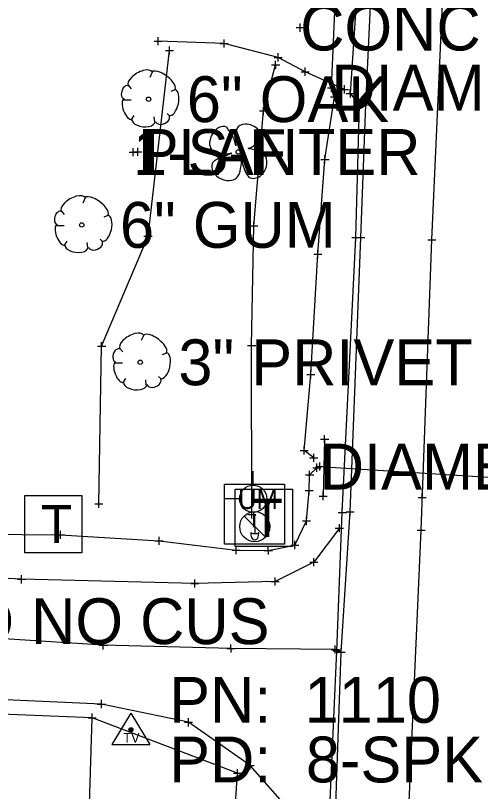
# Model space of a CAD drawing. Extents: x -1 to 1157254, y -1 to 2021979.
# Drawn here: x 1150326.7 to 1150399.8, y 2020191.5 to 2020313.4 of the extents above; entities that cross this region are included whole.
import ezdxf

# ---------------------------------------------------------------- set-up
doc = ezdxf.new("R2010")
doc.units = 0
for name, color, linetype in [('S_BREAKLINE', 7, 'Continuous'), ('S_BUILDING_ANNOT', 7, 'Continuous'), ('S_CAL_CORNER', 7, 'Continuous'), ('S_CATCH_BASIN', 7, 'Continuous'), ('S_CATCH_BASIN_ANNOT', 7, 'Continuous'), ('S_CTL_TABLE', 7, 'Continuous'), ('S_CURB', 7, 'Continuous'), ('S_DRIVEWAY_ANNOT', 7, 'Continuous'), ('S_DROP_INLET_ANNOT', 7, 'Continuous'), ('S_EDGE_BITUMINOUS_ANNOT', 7, 'Continuous'), ('S_EDGE_CONCRETE', 7, 'Continuous'), ('S_EDGE_CONCRETE_ANNOT', 7, 'Continuous'), ('S_ELECTRIC_UTILITIES_ANNOT', 7, 'Continuous'), ('S_ENV_CONSTRAINT', 7, 'Continuous'), ('S_EXIST_ROW', 7, 'Continuous'), ('S_FLAG_POLE', 7, 'Continuous'), ('S_GAS_UTILITIES_ANNOT', 7, 'Continuous'), ('S_GATE', 7, 'Continuous'), ('S_GATE_ANNOT', 7, 'Continuous')]:
    doc.layers.add(name, color=color, linetype=linetype)

msp = doc.modelspace()

# ---------------------------------------------------------------- linework, layer by layer
at = {"layer": 'S_BREAKLINE'}
for p, q in [((1150344.87, 2020203.83), (1150341.86, 2020198.88)), ((1150344.87, 2020203.83), (1150347.82, 2020198.88)), ((1150341.86, 2020198.88), (1150347.82, 2020198.88))]:
    msp.add_line(p, q, dxfattribs=at)
for radius in [0.311, 0.183, 0.103]:
    msp.add_circle((1150344.87, 2020201.23), radius, dxfattribs=at)
at = {"layer": 'S_BUILDING_ANNOT'}
for p, q in [((1150370.81, 2020311.48), (1150372.09, 2020311.48)), ((1150371.45, 2020310.84), (1150371.45, 2020312.11)), ((1150371.45, 2020311.48), (1150371.45, 2020311.48)), ((1150348.5, 2020309.34), (1150349.78, 2020309.34)), ((1150349.14, 2020308.7), (1150349.14, 2020309.97)), ((1150349.14, 2020309.34), (1150349.14, 2020309.34)), ((1150358.85, 2020308.97), (1150360.12, 2020308.97)), ((1150359.49, 2020308.34), (1150359.49, 2020309.61)), ((1150359.49, 2020308.97), (1150359.49, 2020308.97)), ((1150367.35, 2020306.8), (1150368.62, 2020306.8)), ((1150367.99, 2020306.17), (1150367.99, 2020307.44)), ((1150367.99, 2020306.8), (1150367.99, 2020306.8)), ((1150371.58, 2020304.55), (1150372.85, 2020304.55)), ((1150372.22, 2020303.92), (1150372.21, 2020305.19)), ((1150372.21, 2020304.55), (1150372.21, 2020304.55)), ((1150375.72, 2020302.04), (1150377, 2020302.04)), ((1150376.36, 2020301.41), (1150376.36, 2020302.68)), ((1150376.36, 2020302.04), (1150376.36, 2020302.04)), ((1150377.76, 2020301.78), (1150379.04, 2020301.78)), ((1150378.4, 2020301.15), (1150378.4, 2020302.42)), ((1150378.4, 2020301.78), (1150378.4, 2020301.78)), ((1150379.33, 2020300.52), (1150379.32, 2020301.79)), ((1150376.19, 2020300.62), (1150377.46, 2020300.62)), ((1150376.83, 2020299.98), (1150376.82, 2020301.25)), ((1150376.83, 2020300.62), (1150376.83, 2020300.62)), ((1150378.69, 2020301.15), (1150379.96, 2020301.15)), ((1150379.33, 2020301.15), (1150379.33, 2020301.15)), ((1150380.15, 2020299.35), (1150381.43, 2020299.35)), ((1150380.79, 2020298.72), (1150380.79, 2020299.99)), ((1150380.79, 2020299.35), (1150380.79, 2020299.35)), ((1150381.14, 2020299.32), (1150382.42, 2020299.33)), ((1150381.78, 2020298.69), (1150381.78, 2020299.96)), ((1150381.78, 2020299.33), (1150381.78, 2020299.33)), ((1150344.57, 2020291.92), (1150345.84, 2020291.92)), ((1150345.21, 2020291.29), (1150345.2, 2020292.56)), ((1150345.2, 2020291.92), (1150345.2, 2020291.92)), ((1150345.31, 2020291.95), (1150346.58, 2020291.95)), ((1150345.95, 2020291.32), (1150345.95, 2020292.59)), ((1150345.95, 2020291.95), (1150345.95, 2020291.95)), ((1150374.7, 2020290.75), (1150375.98, 2020290.76)), ((1150375.34, 2020290.12), (1150375.34, 2020291.39)), ((1150375.34, 2020290.75), (1150375.34, 2020290.75)), ((1150379.57, 2020278.54), (1150380.84, 2020278.54)), ((1150380.21, 2020277.9), (1150380.2, 2020279.18)), ((1150380.21, 2020278.54), (1150380.21, 2020278.54)), ((1150380.35, 2020278.5), (1150381.63, 2020278.5)), ((1150380.99, 2020277.86), (1150380.99, 2020279.13)), ((1150380.99, 2020278.5), (1150380.99, 2020278.5)), ((1150392.14, 2020277.51), (1150392.13, 2020278.78)), ((1150391.5, 2020278.14), (1150392.77, 2020278.15)), ((1150392.14, 2020278.15), (1150392.14, 2020278.15)), ((1150374.23, 2020275.25), (1150374.22, 2020276.52)), ((1150373.59, 2020275.88), (1150374.86, 2020275.88)), ((1150374.22, 2020275.88), (1150374.22, 2020275.88)), ((1150372.49, 2020257.02), (1150373.76, 2020257.02)), ((1150373.13, 2020256.38), (1150373.13, 2020257.65)), ((1150373.13, 2020257.02), (1150373.13, 2020257.02)), ((1150374.66, 2020246.84), (1150375.93, 2020246.85)), ((1150375.29, 2020246.21), (1150375.29, 2020247.48)), ((1150375.29, 2020246.84), (1150375.29, 2020246.84)), ((1150372.08, 2020244.42), (1150372.08, 2020245.69)), ((1150371.45, 2020245.06), (1150372.72, 2020245.06)), ((1150372.08, 2020245.06), (1150372.08, 2020245.06)), ((1150373.58, 2020243.28), (1150373.58, 2020244.55)), ((1150372.94, 2020243.91), (1150374.21, 2020243.91)), ((1150373.58, 2020243.91), (1150373.58, 2020243.91)), ((1150374.53, 2020241.91), (1150374.53, 2020243.18)), ((1150372.93, 2020240.62), (1150372.93, 2020241.9)), ((1150373.45, 2020242.37), (1150374.72, 2020242.37)), ((1150373.89, 2020242.54), (1150375.16, 2020242.55)), ((1150374.09, 2020241.74), (1150374.09, 2020243.01)), ((1150374.09, 2020242.37), (1150374.09, 2020242.37)), ((1150374.53, 2020242.54), (1150374.53, 2020242.54)), ((1150372.29, 2020241.26), (1150373.57, 2020241.26)), ((1150372.93, 2020241.26), (1150372.93, 2020241.26)), ((1150372.23, 2020238.77), (1150373.5, 2020238.78)), ((1150372.87, 2020238.14), (1150372.86, 2020239.41)), ((1150372.87, 2020238.78), (1150372.87, 2020238.78)), ((1150375.05, 2020237.29), (1150375.05, 2020238.56)), ((1150390.63, 2020237.05), (1150390.62, 2020238.32)), ((1150390.63, 2020237.05), (1150390.62, 2020238.32)), ((1150374.41, 2020237.92), (1150375.68, 2020237.92)), ((1150375.05, 2020237.92), (1150375.05, 2020237.92)), ((1150389.99, 2020237.68), (1150391.26, 2020237.69)), ((1150389.99, 2020237.68), (1150391.26, 2020237.69)), ((1150390.63, 2020237.69), (1150390.63, 2020237.69)), ((1150390.63, 2020237.69), (1150390.63, 2020237.69)), ((1150378.07, 2020234.7), (1150378.07, 2020235.98)), ((1150379.28, 2020234.81), (1150379.28, 2020236.08)), ((1150372.43, 2020233.37), (1150372.42, 2020234.65)), ((1150377.43, 2020235.34), (1150378.7, 2020235.34)), ((1150378.07, 2020235.34), (1150378.07, 2020235.34)), ((1150378.65, 2020235.44), (1150379.92, 2020235.45)), ((1150379.28, 2020235.44), (1150379.28, 2020235.44)), ((1150371.79, 2020234.01), (1150373.06, 2020234.01)), ((1150372.42, 2020234.01), (1150372.42, 2020234.01)), ((1150377.6, 2020232.25), (1150377.6, 2020233.52)), ((1150333.8, 2020231.18), (1150333.79, 2020232.45)), ((1150376.96, 2020232.89), (1150378.24, 2020232.89)), ((1150377.6, 2020232.89), (1150377.6, 2020232.89)), ((1150389.82, 2020232.55), (1150391.09, 2020232.55)), ((1150390.45, 2020231.91), (1150390.45, 2020233.19)), ((1150390.45, 2020232.55), (1150390.45, 2020232.55)), ((1150333.16, 2020231.81), (1150334.43, 2020231.81)), ((1150333.79, 2020231.81), (1150333.79, 2020231.81)), ((1150349.29, 2020230.23), (1150349.29, 2020231.5)), ((1150348.65, 2020230.87), (1150349.93, 2020230.87)), ((1150349.29, 2020230.87), (1150349.29, 2020230.87)), ((1150361.39, 2020228.79), (1150361.39, 2020230.06)), ((1150366.45, 2020228.75), (1150366.44, 2020230.02)), ((1150369.97, 2020230.22), (1150371.24, 2020230.22)), ((1150370.61, 2020229.58), (1150370.6, 2020230.86)), ((1150370.6, 2020230.22), (1150370.6, 2020230.22)), ((1150360.76, 2020229.43), (1150362.03, 2020229.43)), ((1150361.39, 2020229.43), (1150361.39, 2020229.43)), ((1150365.81, 2020229.38), (1150367.08, 2020229.39)), ((1150366.44, 2020229.39), (1150366.44, 2020229.39)), ((1150372.96, 2020227.52), (1150374.23, 2020227.53)), ((1150373.6, 2020226.89), (1150373.6, 2020228.16)), ((1150373.6, 2020227.53), (1150373.6, 2020227.53)), ((1150327.06, 2020224.84), (1150328.33, 2020224.84)), ((1150327.69, 2020224.2), (1150327.69, 2020225.47)), ((1150327.69, 2020224.84), (1150327.69, 2020224.84)), ((1150367.53, 2020223.85), (1150367.53, 2020225.12)), ((1150354.25, 2020224.17), (1150355.52, 2020224.17)), ((1150354.89, 2020223.53), (1150354.88, 2020224.81)), ((1150354.89, 2020224.17), (1150354.89, 2020224.17)), ((1150366.9, 2020224.48), (1150368.17, 2020224.48)), ((1150367.53, 2020224.48), (1150367.53, 2020224.48)), ((1150340.53, 2020213.84), (1150340.53, 2020215.12)), ((1150339.89, 2020214.48), (1150341.17, 2020214.48)), ((1150340.53, 2020214.48), (1150340.53, 2020214.48)), ((1150359.95, 2020213.97), (1150361.22, 2020213.97)), ((1150360.59, 2020213.33), (1150360.58, 2020214.6)), ((1150360.59, 2020213.97), (1150360.59, 2020213.97)), ((1150376.96, 2020213.19), (1150376.96, 2020214.46)), ((1150377.22, 2020212.96), (1150377.21, 2020214.23)), ((1150377.87, 2020212.76), (1150377.87, 2020214.03)), ((1150376.33, 2020213.82), (1150377.6, 2020213.83)), ((1150376.58, 2020213.59), (1150377.85, 2020213.6)), ((1150376.96, 2020213.82), (1150376.96, 2020213.82)), ((1150377.22, 2020213.59), (1150377.22, 2020213.59)), ((1150377.23, 2020213.39), (1150378.51, 2020213.39)), ((1150377.87, 2020213.39), (1150377.87, 2020213.39)), ((1150340.22, 2020204.62), (1150340.22, 2020205.9)), ((1150339.59, 2020205.26), (1150340.86, 2020205.26)), ((1150340.22, 2020205.26), (1150340.22, 2020205.26)), ((1150353.92, 2020201.75), (1150353.92, 2020203.02)), ((1150353.28, 2020202.39), (1150354.55, 2020202.39)), ((1150353.92, 2020202.39), (1150353.92, 2020202.39)), ((1150362.97, 2020195.61), (1150364.24, 2020195.61)), ((1150363.61, 2020194.97), (1150363.61, 2020196.25)), ((1150363.61, 2020195.61), (1150363.61, 2020195.61))]:
    msp.add_line(p, q, dxfattribs=at)
at = {"layer": 'S_CAL_CORNER'}
for p, q in [((1150362.65, 2020234.78), (1150365.99, 2020231.44)), ((1150364.17, 2020235), (1150364.48, 2020235)), ((1150364.32, 2020233.11), (1150364.32, 2020234.84)), ((1150363.72, 2020232.21), (1150363.72, 2020232.02)), ((1150364.32, 2020233.11), (1150364.32, 2020232.05)), ((1150364.92, 2020232.21), (1150364.93, 2020231.98))]:
    msp.add_line(p, q, dxfattribs=at)
msp.add_lwpolyline([(1150359.56, 2020239.77), (1150368.97, 2020239.77), (1150368.97, 2020230.36), (1150359.56, 2020230.36)], close=True, dxfattribs=at)
msp.add_circle((1150364.32, 2020233.11), 2.36, dxfattribs=at)
for centre, radius, start, end in [((1150364.32, 2020235), 0.156, 180, 0), ((1150364.15, 2020232.6), 0.58, 223.1344, 287.472), ((1150364.5, 2020232.61), 0.58, 252.528, 316.8656)]:
    msp.add_arc(centre, radius, start, end, dxfattribs=at)
msp.add_ellipse((1150364.32, 2020231.86), major_axis=(0, -0.82), ratio=0.744362, start_param=4.519801, end_param=8.000179, dxfattribs=at)
at = {"layer": 'S_CATCH_BASIN'}
for p, q in [((1150364.07, 2020239.6), (1150364.07, 2020241.84)), ((1150361.98, 2020237.47), (1150359.65, 2020237.47)), ((1150364.15, 2020233.05), (1150364.15, 2020235.37))]:
    msp.add_line(p, q, dxfattribs=at)
msp.add_circle((1150364.07, 2020237.49), 2.13, dxfattribs=at)
at = {"layer": 'S_CATCH_BASIN_ANNOT'}
for points in [[(1150361.24, 2020230), (1150361.24, 2020239), (1150370.23, 2020239), (1150370.23, 2020230)], [(1150328.18, 2020229.02), (1150328.18, 2020238.02), (1150337.18, 2020238.02), (1150337.18, 2020229.02)]]:
    msp.add_lwpolyline(points, close=True, dxfattribs=at)
at = {"layer": 'S_CTL_TABLE'}
for p, q in [((1150350.28, 2020307.86), (1150351.55, 2020307.86)), ((1150350.92, 2020307.23), (1150350.91, 2020308.5)), ((1150350.91, 2020307.86), (1150350.91, 2020307.86)), ((1150366.97, 2020305.62), (1150368.24, 2020305.62)), ((1150367.61, 2020304.98), (1150367.6, 2020306.25)), ((1150367.6, 2020305.62), (1150367.6, 2020305.62)), ((1150365.05, 2020298.4), (1150366.32, 2020298.41)), ((1150365.69, 2020297.77), (1150365.68, 2020299.04)), ((1150365.69, 2020298.4), (1150365.69, 2020298.4)), ((1150364.16, 2020279.72), (1150364.16, 2020280.99)), ((1150363.52, 2020280.36), (1150364.79, 2020280.36)), ((1150364.16, 2020280.36), (1150364.16, 2020280.36)), ((1150346.91, 2020278.72), (1150348.18, 2020278.73)), ((1150347.55, 2020278.09), (1150347.54, 2020279.36)), ((1150347.55, 2020278.73), (1150347.55, 2020278.73)), ((1150339.63, 2020261.47), (1150340.9, 2020261.47)), ((1150340.27, 2020260.83), (1150340.27, 2020262.1)), ((1150340.27, 2020261.47), (1150340.27, 2020261.47)), ((1150363.18, 2020261.54), (1150364.46, 2020261.54)), ((1150363.82, 2020260.9), (1150363.82, 2020262.18)), ((1150363.82, 2020261.54), (1150363.82, 2020261.54)), ((1150339.84, 2020236.07), (1150339.84, 2020237.34)), ((1150339.21, 2020236.71), (1150340.48, 2020236.71)), ((1150339.84, 2020236.71), (1150339.84, 2020236.71)), ((1150363.21, 2020235.02), (1150364.49, 2020235.02)), ((1150363.85, 2020234.39), (1150363.85, 2020235.66)), ((1150363.85, 2020235.02), (1150363.85, 2020235.02)), ((1150338.14, 2020203.11), (1150339.41, 2020203.11)), ((1150338.15, 2020203.11), (1150339.42, 2020203.11)), ((1150338.78, 2020202.48), (1150338.78, 2020203.75)), ((1150338.78, 2020203.11), (1150338.78, 2020203.11)), ((1150338.79, 2020202.47), (1150338.79, 2020203.75)), ((1150338.79, 2020203.11), (1150338.79, 2020203.11)), ((1150360.99, 2020194.38), (1150362.27, 2020194.39)), ((1150361.63, 2020193.75), (1150361.63, 2020195.02)), ((1150361.63, 2020194.38), (1150361.63, 2020194.38))]:
    msp.add_line(p, q, dxfattribs=at)
at = {"layer": 'S_CURB'}
for p, q in [((1150348.21, 2020304.48), (1150347.83, 2020303.63)), ((1150344.42, 2020302.46), (1150344.92, 2020301.88)), ((1150351.78, 2020301.69), (1150351.12, 2020301.42)), ((1150343.76, 2020300.14), (1150344.88, 2020300.14)), ((1150351, 2020297.58), (1150350.54, 2020298.01)), ((1150344.92, 2020296.96), (1150345.39, 2020297.66)), ((1150348.6, 2020296.69), (1150348.52, 2020297.47)), ((1150361.35, 2020292.93), (1150361.11, 2020293.82)), ((1150363.3, 2020292.47), (1150363.68, 2020292.63)), ((1150360.7, 2020291.77), (1150359.73, 2020291.55)), ((1150362.24, 2020290.84), (1150362.32, 2020290.4)), ((1150337.69, 2020284.75), (1150337.31, 2020283.9)), ((1150333.9, 2020282.73), (1150334.4, 2020282.15)), ((1150341.26, 2020281.96), (1150340.6, 2020281.69)), ((1150333.24, 2020280.41), (1150334.36, 2020280.41)), ((1150334.4, 2020277.23), (1150334.87, 2020277.93)), ((1150338.08, 2020276.96), (1150338, 2020277.74)), ((1150340.48, 2020277.85), (1150340.02, 2020278.28)), ((1150346.88, 2020263.17), (1150346.49, 2020262.32)), ((1150343.08, 2020261.15), (1150343.59, 2020260.57)), ((1150350.44, 2020260.38), (1150349.78, 2020260.11)), ((1150342.42, 2020258.83), (1150343.55, 2020258.83)), ((1150349.67, 2020256.27), (1150349.2, 2020256.7)), ((1150343.59, 2020255.65), (1150344.05, 2020256.35)), ((1150347.27, 2020255.38), (1150347.19, 2020256.16))]:
    msp.add_line(p, q, dxfattribs=at)
for centre in [(1150347.65, 2020300.24), (1150361.72, 2020291.95), (1150337.14, 2020280.5), (1150346.32, 2020258.92)]:
    msp.add_circle(centre, 0.34, dxfattribs=at)
for centre, major_axis, ratio, start_param, end_param in [((1150346.32, 2020303.44), (1.86, 1.08), 0.471018, 0, 3.141593), ((1150349.97, 2020303.11), (-1.81, 1.36), 0.405113, 3.141593, 6.283186), ((1150344.09, 2020301.32), (0.31, 1.03), 0.646762, 0, 3.141593), ((1150351.33, 2020299.71), (0.46, 2.04), 0.482994, 3.141593, 6.283185), ((1150344.39, 2020298.67), (-0.61, 1.6), 0.420543, 6.283185, 9.424777), ((1150346.85, 2020296.89), (-1.83, 0.19), 0.529943, 0, 3.141593), ((1150349.81, 2020297.19), (1.09, 0.46), 0.711534, 3.141592, 6.283185), ((1150358.84, 2020293.97), (-1.03, -1.88), 0.662338, 3.141593, 6.283185), ((1150360.49, 2020294.84), (0.62, -1.01), 0.083512, 0, 3.141593), ((1150361.42, 2020294.26), (-0.07, -1.33), 0.068203, 3.141593, 6.283185), ((1150363.38, 2020294.84), (1.89, -0.74), 0.673998, 0, 3.141593), ((1150364.48, 2020293.36), (-0.798, -0.73), 0.092159, 0, 3.141593), ((1150358.77, 2020291.82), (0.963, -0.267), 0.113563, 3.141593, 6.283185), ((1150364.26, 2020292.24), (0.96, -0.23), 0.056001, 0, 3.141593), ((1150364.34, 2020289.97), (0.88, 2.05), 0.81717, 3.141593, 6.283185), ((1150358.15, 2020290.56), (0.477, 0.328), 0.136309, 0, 3.141593), ((1150359.67, 2020291.33), (1.04, 0.44), 0.002756, 3.141593, 6.283185), ((1150362, 2020289.67), (0.19, 1.31), 0.114148, 3.141593, 5.822668), ((1150359.74, 2020289.29), (2.07, -0.93), 0.760068, 3.141593, 6.283185), ((1150362.57, 2020289.63), (0.254, -0.771), 0.051603, 3.141593, 6.283185), ((1150363.15, 2020288.39), (-0.321, 0.467), 0.094289, 0, 3.141593), ((1150335.8, 2020283.7), (1.86, 1.08), 0.471018, 0, 3.141593), ((1150339.45, 2020283.38), (-1.81, 1.36), 0.405113, 3.141593, 6.283186), ((1150333.57, 2020281.59), (0.31, 1.03), 0.646762, 0, 3.141593), ((1150340.81, 2020279.97), (0.46, 2.04), 0.482994, 3.141593, 6.283185), ((1150333.87, 2020278.94), (-0.61, 1.6), 0.420543, 6.283185, 9.424777), ((1150336.33, 2020277.16), (-1.83, 0.19), 0.529943, 0, 3.141593), ((1150339.29, 2020277.45), (1.09, 0.46), 0.711534, 3.141592, 6.283185), ((1150344.98, 2020262.12), (1.86, 1.08), 0.471018, 0, 3.141593), ((1150348.64, 2020261.8), (-1.81, 1.36), 0.405113, 3.141593, 6.283186), ((1150342.75, 2020260.01), (0.31, 1.03), 0.646762, 0, 3.141593), ((1150349.99, 2020258.39), (0.46, 2.04), 0.482994, 3.141593, 6.283185), ((1150343.06, 2020257.36), (-0.61, 1.6), 0.420543, 6.283185, 9.424777), ((1150345.52, 2020255.58), (-1.83, 0.19), 0.529943, 0, 3.141593), ((1150348.47, 2020255.87), (1.09, 0.46), 0.711534, 3.141592, 6.283185)]:
    msp.add_ellipse(centre, major_axis=major_axis, ratio=ratio, start_param=start_param, end_param=end_param, dxfattribs=at)
at = {"layer": 'S_DRIVEWAY_ANNOT'}
for points in [[(1150373.58, 2020243.91), (1150372.08, 2020245.06), (1150373.13, 2020257.02), (1150374.22, 2020275.88), (1150375.34, 2020290.75), (1150376.83, 2020300.62)], [(1150309.59, 2020232.06), (1150333.79, 2020231.81), (1150349.29, 2020230.87), (1150361.39, 2020229.43), (1150366.44, 2020229.39), (1150370.6, 2020230.22), (1150372.42, 2020234.01), (1150372.87, 2020238.78), (1150372.93, 2020241.26), (1150374.09, 2020242.37)]]:
    msp.add_lwpolyline(points, dxfattribs=at)
at = {"layer": 'S_DROP_INLET_ANNOT'}
msp.add_lwpolyline([(1150376.36, 2020302.04), (1150377.13, 2020320.03)], dxfattribs=at)
at = {"layer": 'S_EDGE_BITUMINOUS_ANNOT'}
for points in [[(1150339.84, 2020236.71), (1150340.27, 2020261.47), (1150347.55, 2020278.73), (1150350.91, 2020307.86)], [(1150363.85, 2020235.02), (1150363.82, 2020261.54), (1150364.16, 2020280.36), (1150365.69, 2020298.4), (1150367.6, 2020305.62)], [(1150357.45, 2020078.92), (1150358.97, 2020104.94), (1150359.07, 2020139.54), (1150360.26, 2020173.71), (1150361.63, 2020194.38), (1150338.79, 2020203.11), (1150311.34, 2020204.19), (1150285.41, 2020205)], [(1150338.71, 2020076.04), (1150342.08, 2020105.19), (1150338.63, 2020140.72), (1150337.82, 2020172.57), (1150338.78, 2020203.11)]]:
    msp.add_lwpolyline(points, dxfattribs=at)
at = {"layer": 'S_EDGE_CONCRETE'}
for points in [[(1150369.08, 2020017.27), (1150370.27, 2020039.2), (1150371.48, 2020060.47), (1150372.35, 2020085.18), (1150374.19, 2020124.19), (1150376.4, 2020171.41), (1150377.87, 2020213.39), (1150379.28, 2020235.44), (1150380.99, 2020278.5), (1150381.78, 2020299.33), (1150382.85, 2020322.68), (1150383.16, 2020327.3), (1150384.87, 2020364.96), (1150387.44, 2020433.07)], [(1150377.6, 2020232.89), (1150373.6, 2020227.53), (1150367.53, 2020224.48), (1150354.89, 2020224.17), (1150327.69, 2020224.84), (1150302.4, 2020226.14), (1150261.15, 2020229.35), (1150223.67, 2020228.92), (1150183.34, 2020230.29), (1150144.2, 2020231.28), (1150095.62, 2020233.53)], [(1150376.1, 2020175.29), (1150374.34, 2020182.07), (1150369.84, 2020188.52), (1150363.61, 2020195.61), (1150353.92, 2020202.39), (1150340.22, 2020205.26), (1150325.22, 2020205.91), (1150301.63, 2020206.19), (1150261.53, 2020207.42), (1150221.68, 2020207.35), (1150183.11, 2020208.06), (1150141.65, 2020210.13), (1150094.5, 2020210.78)]]:
    msp.add_lwpolyline(points, dxfattribs=at)
at = {"layer": 'S_EDGE_CONCRETE_ANNOT'}
for points in [[(1150380.68, 2020016.4), (1150381.98, 2020039.8), (1150384.11, 2020086.8), (1150385.79, 2020123.87), (1150387.85, 2020173.28), (1150390.45, 2020232.55), (1150392.14, 2020278.15), (1150394.26, 2020325.73), (1150396.07, 2020363.7), (1150398.8, 2020432.55)], [(1150376.96, 2020213.82), (1150360.59, 2020213.97), (1150340.53, 2020214.48), (1150325.79, 2020215.45), (1150301.59, 2020216.27), (1150262.07, 2020217.72), (1150223.53, 2020218.58), (1150183.21, 2020219.5), (1150142.56, 2020221.06), (1150094.65, 2020222.47)]]:
    msp.add_lwpolyline(points, dxfattribs=at)
at = {"layer": 'S_ELECTRIC_UTILITIES_ANNOT'}
msp.add_lwpolyline([(1150375.29, 2020246.84), (1150375.05, 2020237.92)], dxfattribs=at)
at = {"layer": 'S_ENV_CONSTRAINT'}
msp.add_lwpolyline([(1150378.4, 2020301.78), (1150372.21, 2020304.55), (1150367.99, 2020306.8), (1150359.49, 2020308.97), (1150349.14, 2020309.34)], dxfattribs=at)
at = {"layer": 'S_EXIST_ROW'}
msp.add_lwpolyline([(1150374.53, 2020242.54), (1150404.34, 2020240.68)], dxfattribs=at)
at = {"layer": 'S_FLAG_POLE'}
msp.add_lwpolyline([(1150368.2, 2020017.11), (1150369.27, 2020040.07), (1150368.26, 2020042.76), (1150369.22, 2020059.76), (1150369.84, 2020083.45), (1150371.61, 2020087.04), (1150373.25, 2020124.14), (1150375.34, 2020171.32), (1150377.22, 2020213.59), (1150378.07, 2020235.34), (1150380.21, 2020278.54), (1150380.79, 2020299.35), (1150379.33, 2020301.15), (1150380.65, 2020320.91), (1150381.61, 2020322.94), (1150382.23, 2020327.2), (1150384.01, 2020365.09), (1150386.74, 2020432.99)], dxfattribs=at)

# ---------------------------------------------------------------- texts
at = {"layer": 'S_BREAKLINE'}
msp.add_text('TV', height=1.499, dxfattribs=at).set_placement((1150343.67, 2020199.21))
at = {"layer": 'S_BUILDING_ANNOT'}
for s, p in [('DIAMETER?12"', (1150376.36, 2020298.44)), ('DIAMETER?30"', (1150374.53, 2020238.94))]:
    msp.add_text(s, height=7.2, dxfattribs=at).set_placement(p)
at = {"layer": 'S_CAL_CORNER'}
msp.add_text('UM', height=2.999, dxfattribs=at).set_placement((1150361.7, 2020235.89))
at = {"layer": 'S_CATCH_BASIN_ANNOT'}
for p in [(1150363.8, 2020231.5), (1150330.74, 2020230.52)]:
    msp.add_text('T', height=6, dxfattribs=at).set_placement(p)
at = {"layer": 'S_GAS_UTILITIES_ANNOT'}
for s, p in [('PN: ', (1150350.87, 2020202.31)), ('1110', (1150372.14, 2020202.31)), ('PD: ', (1150350.87, 2020192.95)), ('8-SPK RBR ALUM CAP 8SPK', (1150372.35, 2020192.95))]:
    msp.add_text(s, height=7.2, dxfattribs=at).set_placement(p)
at = {"layer": 'S_GATE'}
for s, p in [('CONC DW', (1150371.45, 2020307.88)), ('1-S-F', (1150345.2, 2020288.32)), ('PLANTER', (1150345.95, 2020288.35)), ('SCOTT-SALEM RD NO CUS', (1150241.46, 2020214.66))]:
    msp.add_text(s, height=7.2, dxfattribs=at).set_placement(p)
at = {"layer": 'S_GATE_ANNOT'}
for s, p in [('6" OAK', (1150353.65, 2020296.64)), ('6" GUM', (1150343.14, 2020276.9)), ('3" PRIVET', (1150352.32, 2020255.32))]:
    msp.add_text(s, height=7.2, dxfattribs=at).set_placement(p)

doc.saveas('drawing.dxf')
